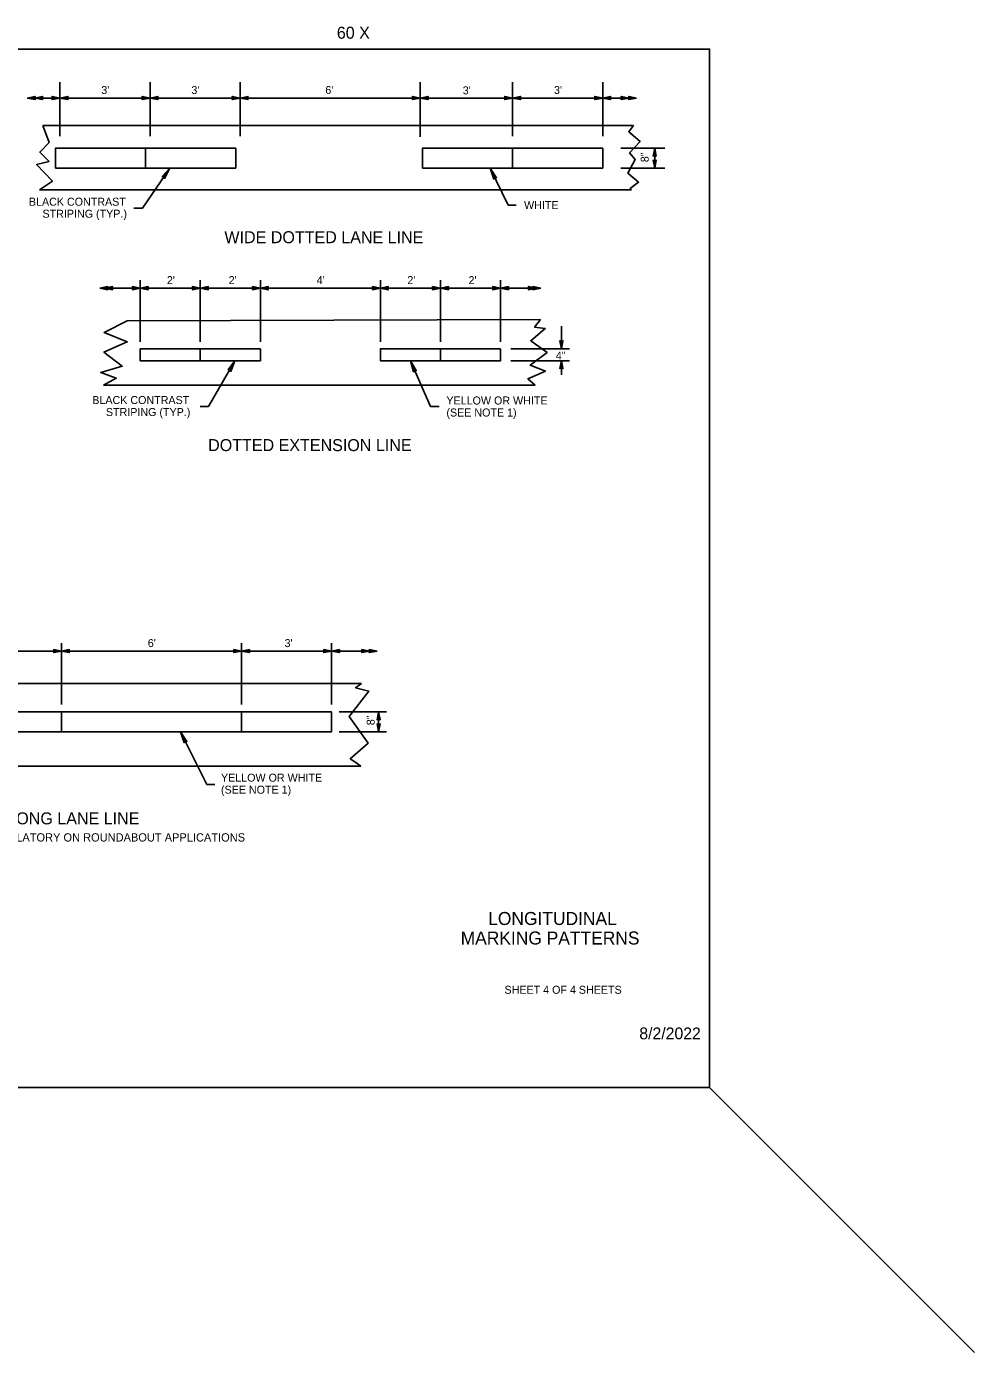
# Model space of a CAD drawing. Extents: x 99754 to 103681, y 99470 to 110996.
# Drawn here: x 101787 to 103681, y 108345 to 110996 of the extents above; entities that cross this region are included whole.
import ezdxf

# ---------------------------------------------------------------- set-up
doc = ezdxf.new("R2010")
doc.units = 0
for name, color, linetype in [('Level 1', 7, 'Continuous'), ('Level 12', 7, 'Continuous'), ('Level 15', 7, 'Continuous'), ('Level 2', 7, 'Continuous'), ('Level 20', 7, 'Continuous'), ('Level 6', 7, 'Continuous'), ('Level 60', 7, 'Continuous'), ('Level 62', 7, 'Continuous'), ('Level 7', 7, 'Continuous')]:
    doc.layers.add(name, color=color, linetype=linetype)

msp = doc.modelspace()

# ---------------------------------------------------------------- linework, layer by layer
at = {"layer": 'Level 1'}
msp.add_line((103151, 108875.5), (103681.3, 108345.2), dxfattribs=at)
msp.add_lwpolyline([(99863, 108875), (103152, 108875), (103152, 110951), (99863, 110951)], close=True, dxfattribs=at)
at = {"layer": 'Level 12'}
for points in [[(101788.2, 110853.1), (101803.9, 110850), (101803.2, 110853.1), (101803.9, 110856.2)], [(101803.2, 110853.1), (101818.9, 110850), (101818.2, 110853.1), (101818.9, 110856.2)], [(101853.7, 110853.1), (101838, 110856.2), (101838.7, 110853.1), (101838, 110850)], [(101853.7, 110853.1), (101869.5, 110850), (101868.7, 110853.1), (101869.5, 110856.2)], [(102033.7, 110853.1), (102018, 110856.2), (102018.7, 110853.1), (102018, 110850)], [(102033.7, 110853.1), (102049.5, 110850), (102048.7, 110853.1), (102049.5, 110856.2)], [(102213.7, 110853.1), (102198, 110856.2), (102198.7, 110853.1), (102198, 110850)], [(102213.7, 110853.1), (102229.5, 110850), (102228.7, 110853.1), (102229.5, 110856.2)], [(102573.7, 110853.1), (102558, 110856.2), (102558.7, 110853.1), (102558, 110850)], [(102573.7, 110853.1), (102558, 110856.2), (102558.7, 110853.1), (102558, 110850)], [(102573.7, 110853.1), (102589.5, 110850), (102588.7, 110853.1), (102589.5, 110856.2)], [(102758.4, 110853.1), (102742.6, 110856.2), (102743.4, 110853.1), (102742.6, 110850)], [(102758.4, 110853.1), (102774.1, 110850), (102773.4, 110853.1), (102774.1, 110856.2)], [(102938.4, 110853.1), (102922.6, 110856.2), (102923.4, 110853.1), (102922.6, 110850)], [(102938.4, 110853.1), (102954.1, 110850), (102953.4, 110853.1), (102954.1, 110856.2)], [(102991.1, 110853.1), (102975.3, 110856.2), (102976.1, 110853.1), (102975.3, 110850)], [(103006.1, 110853.1), (102990.3, 110856.2), (102991.1, 110853.1), (102990.3, 110850)], [(103042.3, 110752.9), (103045.4, 110737.2), (103042.3, 110737.9), (103039.2, 110737.2)], [(103042.3, 110713.1), (103039.2, 110728.8), (103042.3, 110728.1), (103045.4, 110728.8)]]:
    msp.add_lwpolyline(points, close=True, dxfattribs=at)
at = {"layer": 'Level 15'}
for p, q in [((101853.7, 110885.1), (101853.7, 110777.1)), ((102033.7, 110885.1), (102033.7, 110777.1)), ((102213.7, 110885.1), (102213.7, 110777.1)), ((102573.7, 110885.1), (102573.7, 110775.6)), ((102758.4, 110885.1), (102758.4, 110777.1)), ((102938.4, 110885.1), (102938.4, 110777.1)), ((101853.7, 110853.1), (101788.2, 110853.1)), ((102033.7, 110853.1), (101853.7, 110853.1)), ((102213.7, 110853.1), (102033.7, 110853.1)), ((102573.7, 110853.1), (102213.7, 110853.1)), ((102758.4, 110853.1), (102573.7, 110853.1)), ((102938.4, 110853.1), (102758.4, 110853.1)), ((103006.1, 110853.1), (102938.4, 110853.1)), ((102974.6, 110753.1), (103062.3, 110753.1)), ((103042.3, 110752.9), (103042.3, 110713.1)), ((102073.3, 110713.1), (102018.6, 110632.6)), ((102713.4, 110713.1), (102749.2, 110638.7)), ((102974.6, 110713.1), (103062.3, 110713.1)), ((102001.2, 110632.6), (102018.6, 110632.6)), ((102749.2, 110638.7), (102765.2, 110638.7)), ((102014.2, 110473), (101933.6, 110473)), ((102014.2, 110489), (102014.2, 110365.8)), ((102134.2, 110473), (102014.2, 110473)), ((102134.2, 110489), (102134.2, 110365.8)), ((102254.2, 110473), (102134.2, 110473)), ((102254.2, 110489), (102254.2, 110365.8)), ((102494.2, 110473), (102254.2, 110473)), ((102494.2, 110489), (102494.2, 110365.8)), ((102614.2, 110473), (102494.2, 110473)), ((102614.2, 110489), (102614.2, 110365.8)), ((102734.2, 110473), (102614.2, 110473)), ((102734.2, 110489), (102734.2, 110365.8)), ((102735.3, 110473), (102814.5, 110473)), ((102855.9, 110396.8), (102855.9, 110352)), ((102755, 110352), (102871.9, 110352)), ((102203.5, 110328), (102150.5, 110236.3)), ((102554.2, 110328), (102594.3, 110236.7)), ((102755, 110328), (102871.9, 110328)), ((102855.9, 110328), (102855.9, 110299.4)), ((102134.2, 110236.4), (102150.4, 110236.4)), ((102594.3, 110236.7), (102611.4, 110236.7)), ((101856.9, 109747.4), (101676.9, 109747.4)), ((102216.6, 109747.4), (101856.6, 109747.4)), ((101856.9, 109763.4), (101856.9, 109640.3)), ((102216.6, 109763.4), (102216.6, 109640.3)), ((102396.6, 109747.4), (102216.6, 109747.4)), ((102396.6, 109763.4), (102396.6, 109640.3)), ((102487.5, 109747.4), (102396.6, 109747.4)), ((102411.9, 109626), (102506.6, 109626)), ((102490.6, 109626), (102490.6, 109586)), ((102094.5, 109586), (102147.4, 109480.6)), ((102411.9, 109586), (102506.6, 109586)), ((102147.4, 109480.6), (102163.4, 109480.6))]:
    msp.add_line(p, q, dxfattribs=at)
msp.add_lwpolyline([(102814.5, 110473), (102798.8, 110469.9), (102799.5, 110473), (102798.8, 110476.1)], close=True, dxfattribs=at)
at = {"layer": 'Level 2'}
for points in [[(102204.9, 110753.1), (102204.9, 110713.1), (102024.9, 110713.1), (102024.9, 110753.1), (102204.9, 110753.1)], [(102938.4, 110753.1), (102938.4, 110713.1), (102758.4, 110713.1), (102758.4, 110753.1), (102938.4, 110753.1)], [(102254.2, 110352), (102254.2, 110328), (102134.2, 110328), (102134.2, 110352), (102254.2, 110352)], [(102734.2, 110352), (102734.2, 110328), (102614.2, 110328), (102614.2, 110352), (102734.2, 110352)], [(101856.9, 109626), (101856.9, 109586), (101676.9, 109586), (101676.9, 109626), (101856.9, 109626)], [(102396.6, 109626), (102396.6, 109586), (102216.6, 109586), (102216.6, 109626), (102396.6, 109626)]]:
    msp.add_lwpolyline(points, dxfattribs=at)
at = {"layer": 'Level 20'}
for points in [[(102073.3, 110713.1), (102058, 110695.9), (102061.1, 110695.1), (102062.9, 110692.5)], [(102713.4, 110713.1), (102726, 110693.8), (102722.8, 110693.5), (102720.6, 110691.2)], [(101933.6, 110473), (101949.3, 110469.9), (101948.6, 110473), (101949.3, 110476.1)], [(101943.3, 110473), (101959, 110469.9), (101958.3, 110473), (101959, 110476.1)], [(102014.2, 110473), (101998.5, 110476.1), (101999.2, 110473), (101998.5, 110469.9)], [(102014.2, 110473), (102029.9, 110469.9), (102029.2, 110473), (102029.9, 110476.1)], [(102134.2, 110473), (102118.5, 110476.1), (102119.2, 110473), (102118.5, 110469.9)], [(102134.2, 110473), (102149.9, 110469.9), (102149.2, 110473), (102149.9, 110476.1)], [(102254.2, 110473), (102238.5, 110476.1), (102239.2, 110473), (102238.5, 110469.9)], [(102254.2, 110473), (102269.9, 110469.9), (102269.2, 110473), (102269.9, 110476.1)], [(102494.2, 110473), (102478.5, 110476.1), (102479.2, 110473), (102478.5, 110469.9)], [(102494.2, 110473), (102509.9, 110469.9), (102509.2, 110473), (102509.9, 110476.1)], [(102614.2, 110473), (102598.5, 110476.1), (102599.2, 110473), (102598.5, 110469.9)], [(102614.2, 110473), (102629.9, 110469.9), (102629.2, 110473), (102629.9, 110476.1)], [(102734.2, 110473), (102718.5, 110476.1), (102719.2, 110473), (102718.5, 110469.9)], [(102734.2, 110473), (102749.9, 110469.9), (102749.2, 110473), (102749.9, 110476.1)], [(102805.6, 110473), (102789.9, 110476.1), (102790.6, 110473), (102789.9, 110469.9)], [(102855.9, 110352), (102859, 110367.8), (102855.9, 110367), (102852.9, 110367.8)], [(102203.5, 110328), (102189.9, 110309.5), (102193, 110309), (102195.1, 110306.6)], [(102554.2, 110328), (102565.8, 110308.2), (102562.7, 110308), (102560.3, 110305.9)], [(102855.9, 110328), (102852.9, 110312.3), (102855.9, 110313), (102859, 110312.3)], [(101856.9, 109747.4), (101841.2, 109750.5), (101841.9, 109747.4), (101841.2, 109744.3)], [(101856.6, 109747.4), (101872.3, 109744.3), (101871.6, 109747.4), (101872.3, 109750.5)], [(102216.6, 109747.4), (102200.9, 109750.5), (102201.6, 109747.4), (102200.9, 109744.3)], [(102216.6, 109747.4), (102232.3, 109744.3), (102231.6, 109747.4), (102232.3, 109750.5)], [(102396.6, 109747.4), (102380.9, 109750.5), (102381.6, 109747.4), (102380.9, 109744.3)], [(102396.6, 109747.4), (102412.3, 109744.3), (102411.6, 109747.4), (102412.3, 109750.5)], [(102472.5, 109747.4), (102456.8, 109750.5), (102457.5, 109747.4), (102456.8, 109744.3)], [(102487.5, 109747.4), (102471.8, 109750.5), (102472.5, 109747.4), (102471.8, 109744.3)], [(102490.6, 109626), (102493.7, 109610.2), (102490.6, 109611), (102487.5, 109610.2)], [(102490.6, 109586), (102487.5, 109601.7), (102490.6, 109601), (102493.7, 109601.7)], [(102094.5, 109586), (102107.4, 109566.9), (102104.3, 109566.5), (102102.1, 109564.2)]]:
    msp.add_lwpolyline(points, close=True, dxfattribs=at)
at = {"layer": 'Level 6'}
for points in [[(102024.9, 110753.1), (102024.9, 110713.1), (101844.9, 110713.1), (101844.9, 110753.1), (102024.9, 110753.1)], [(102758.4, 110753.1), (102758.4, 110713.1), (102668.4, 110713.1), (102578.4, 110713.1), (102578.4, 110753.1), (102758.4, 110753.1)], [(102134.2, 110352), (102134.2, 110328), (102014.2, 110328), (102014.2, 110352), (102134.2, 110352)], [(102614.2, 110352), (102614.2, 110328), (102494.2, 110328), (102494.2, 110352), (102614.2, 110352)], [(102216.6, 109626), (102216.6, 109586), (101856.6, 109586), (101856.6, 109626), (102216.6, 109626)]]:
    msp.add_lwpolyline(points, dxfattribs=at)
at = {"layer": 'Level 60'}
msp.add_line((103152, 110951), (103152, 110951), dxfattribs=at)
at = {"layer": 'Level 7'}
for p, q in [((103000, 110797.9), (101819.4, 110797.9)), ((101813, 110669.8), (102995.8, 110669.8)), ((102814, 110410.2), (101988.2, 110407.9)), ((101940.9, 110278.8), (102803.5, 110278.8)), ((102456.2, 109682.3), (101246.5, 109682.3)), ((101256.7, 109517.2), (102454.8, 109517.2))]:
    msp.add_line(p, q, dxfattribs=at)
for points in [[(101819.4, 110797.9), (101832, 110764.1), (101813.4, 110745), (101832, 110726.4), (101806.9, 110720.4), (101838.5, 110687.2), (101813, 110669.8)], [(102995.8, 110669.8), (102993.1, 110672.2), (103009.9, 110684.7), (102988.9, 110702.7), (103003, 110730.3), (102992.2, 110743.3), (103013, 110766.4), (102990.5, 110785.8), (103000, 110797.9)], [(102803.5, 110278.8), (102789, 110291.8), (102823.8, 110307.2), (102793.5, 110318.8), (102827.1, 110344.2), (102794.5, 110367.8), (102823.5, 110392.2), (102802.1, 110395.1), (102814, 110410.2)], [(101988.2, 110407.9), (101941.7, 110384.3), (101988.2, 110365.6), (101941.5, 110345.1), (101978.1, 110316.8), (101935.2, 110304.3), (101966.3, 110292.8), (101940.9, 110278.8)], [(102454.8, 109517.2), (102443.3, 109526), (102433.9, 109532.3), (102469.4, 109563.3), (102431.7, 109616.7), (102470.9, 109667.6), (102444.5, 109674), (102456.2, 109682.3)]]:
    msp.add_lwpolyline(points, dxfattribs=at)

# ---------------------------------------------------------------- texts
at = {"layer": 'Level 15'}
for s, height, p in [('60 X', 24, (102407, 110971.7)), ('8/2/2022', 23.62, (103011.5, 108971.3))]:
    msp.add_text(s, height=height, dxfattribs=at).set_placement(p)
at = {"layer": 'Level 20'}
for s, height, p in [("3'", 16, (101936.3, 110861.1)), ("3'", 16, (102116.3, 110861.1)), ("6'", 16, (102384, 110861.1)), ("3'", 16, (102658.6, 110860.4)), ("3'", 16, (102841, 110861.1)), ('BLACK CONTRAST ', 16, (101791.6, 110637.8)), ('STRIPING (TYP.)', 16, (101818.8, 110613.8)), ('WHITE', 16, (102781.2, 110631)), ('WIDE DOTTED LANE LINE', 24, (102182.3, 110562.9)), ("2'", 16, (102067.4, 110481)), ("2'", 16, (102190.8, 110481)), ("4'", 16, (102366.8, 110481)), ("2'", 16, (102547.9, 110481)), ("2'", 16, (102670.2, 110481)), ('BLACK CONTRAST ', 16, (101918.3, 110241.3)), ('YELLOW OR WHITE  ', 16, (102626, 110240.4)), ('STRIPING (TYP.)', 16, (101945.5, 110217.3)), ('(SEE NOTE 1)', 16, (102626, 110216.4)), ('DOTTED EXTENSION LINE', 24, (102149.8, 110147.2)), ("6'", 16, (102029.2, 109755.4)), ("3'", 16, (102302.6, 109755.4)), ('YELLOW OR WHITE', 16, (102175.5, 109486.3)), ('(SEE NOTE 1)', 16, (102175.5, 109462.3)), ('STRONG LANE LINE', 24, (101702.2, 109401)), ('OPTION TO USE AS CIRCULATORY ON ROUNDABOUT APPLICATIONS', 16.5, (101481.9, 109366.7))]:
    msp.add_text(s, height=height, dxfattribs=at).set_placement(p)
for s, rotation, p in [('8"', 90, (103030.3, 110724.8)), ('4"', 360, (102844.6, 110330.2)), ('8"', 90, (102482.6, 109599.2))]:
    msp.add_text(s, height=16, rotation=rotation, dxfattribs=at).set_placement(p)
at = {"layer": 'Level 62'}
for s, height, p in [('LONGITUDINAL ', 26, (102709.5, 109199.8)), ('MARKING PATTERNS', 26, (102654.5, 109160.8)), ('SHEET 4 OF 4 SHEETS', 16, (102742.1, 109062.3))]:
    msp.add_text(s, height=height, dxfattribs=at).set_placement(p)

doc.saveas('drawing.dxf')
